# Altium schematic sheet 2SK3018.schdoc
size 127 x 101 mm
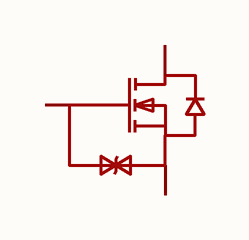
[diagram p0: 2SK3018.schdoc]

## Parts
Q?  2sk3018_c8562  [SOT-23-3_L2.9-W1.3-P1.90-LS2.4-BR]  (value not drawn)

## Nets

Not connected (* = marked no-connect by the designer): Q? 1(G) 2(S) 3(D)

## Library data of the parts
Q? = 2sk3018_c8562: 数量:1个N沟道;漏源电压(Vdss):30V;连续漏极电流(Id):100mA;导通电阻(RDS(on)):13Ω@2.5V;耗散功率(Pd):350mW;阈值电压(Vgs(th)):800mV;; Manufacturer: CJ(江苏长电/长晶); AddInBom: yes; ModelId: c62791f0466c4ae2a892c056b845b0ca; ModelName: SOT-23-3P_L2.9-W1.3-H1.0-LS2.4-P0.95; ModelTransform: 98.425,114.173,0,180,0,0,0.0005,-0.0005,0; Number: 1个N沟道; Drain to Source Voltage: 30V; Current - Continuous Drain(Id): 100mA; Pd - Power Dissipation: 350mW; Gate Threshold Voltage (Vgs(th)): 800mV; Input Capacitance(Ciss): 13pF; Reverse Transfer Capacitance (Crss@Vds): 4pF; Type: N沟道; Output Capacitance(Coss): 9pF; Vgs: ±20V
